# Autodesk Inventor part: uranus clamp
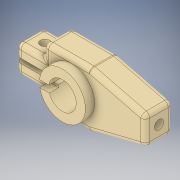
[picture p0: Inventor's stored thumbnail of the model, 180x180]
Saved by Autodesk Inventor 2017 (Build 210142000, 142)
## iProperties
Created: 2016-05
Part Number: uranus clamp
Material: Generic
Document SubType Name: Modeling
Designer: Stan
Density: 1 g/cm^3
Appearance: Beige
Author: Stan
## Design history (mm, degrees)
sketch "Sketch1"
  geometry: L1 (-9.525, 9.525)-(6.35, 9.525); L2 (6.35, -9.463)-(-9.525, -9.463); L3 (25.4, 4.763)-(25.4, -4.763); L4 (25.4, -4.763)-(6.35, -9.463); L5 (25.4, 4.763)-(6.35, 9.525); L6 (-9.525, 9.525)-(-9.525, 4.763); L7 (-9.525, 4.763)-(-19.05, 4.762); L8 (-19.05, -4.7)-(-9.525, -4.7); L9 (-9.525, -4.7)-(-9.525, -9.463); L10 (-4.701, 0.762)-(-19.05, 0.762); L11 (-4.701, -0.762)-(-19.05, -0.762); L12 (-19.05, -4.7)-(-19.05, -0.762); L13 (-19.05, 0.762)-(-19.05, 4.762); A1 r 4.763 centre (0, 0) between (-4.701, -0.762) and (-4.701, 0.762); 1 further point
  constraints: 26 end point, 4 perpendicular, 2 point on circle, 2 point on line, 2 vertical, 1 centre point, 1 coincident, 1 horizontal, 1 parallel
  dimensions: "d1" = 9.525 distance from line of L1 point (0, 0); "d2" = 25.4 horizontal distance of L3.end point (0, 0); "d4" = 9.525 distance of L3.start L3.end; "d5" = 4.7625 vertical distance of point (0, 0) L3.start; "d7" = 9.525 diameter of A1; "d8" = 19.05 horizontal distance of L8.start point (0, 0); "d11" = 9.525 distance from line of point (0, 0) L6; "d12" = 19.05 distance from line of point (0, 0) L13; "d14" = 1.524 distance between parallel lines of L11 L10; "d15" = 0.762 distance from line of L10 point (0, 0); "d16" = 15.875 distance of L1.start L1.end; "d17" = 15.875 distance of L2.start L2.end; "d18" = 4.7625 distance between parallel lines of L2 L8; "d19" = 4.7625 distance between parallel lines of L7 L1
extrude "Extrusion1" new body sketch "Sketch1" distance "d20" = 9.525; taper "d21" = 0 deg
fillet "Fillet1" dims "d22" = 1.5875
sketch "Sketch2"
  geometry: C1 r 1.587 at (3.175, 3.519); 1 further point
  constraints: 1 centre point
  dimensions: "d23" = 3.175 diameter of C1
extrude "Extrusion2" cut sketch "Sketch2" distance "d24" = 15.875; taper "d25" = 0 deg
sketch "Sketch3"
  geometry: L1 (-1.587, 6.35)-(-1.588, 0) reference; C1 r 1.587 at (3.492, 3.175); 1 further point
  constraints: 1 centre point
  dimensions: "d26" = 3.175 diameter of C1; "d27" = 5.08 distance from line of C1.centre L1
extrude "Extrusion3" cut sketch "Sketch3" distance "d28" = 9.525; taper "d29" = 0 deg
fillet "Fillet2" dims "d30" = 1.5875
fillet "Fillet3" dims "d31" = 1.5875
sketch "Sketch4"
  geometry: L1 (-4.701, 0.762)-(-7.901, 0.762); L2 (-17.462, 0.762)-(-4.701, 0.762) reference; L3 (-4.512, -1.524)-(-7.79, -1.524); A1 r 7.938 centre (0, 0) between (-7.79, -1.524) and (-7.901, 0.762); A2 r 4.763 centre (0, 0) between (-4.512, -1.524) and (-4.701, 0.762); 1 further point
  constraints: 5 end point, 4 point on circle, 2 centre point, 2 coincident, 1 parallel, 1 point on line
  dimensions: "d32" = 15.875 diameter of A1
extrude "Extrusion4" join sketch "Sketch4" distance "d33" = 3.175; taper "d34" = 0 deg
body "Solid1"
